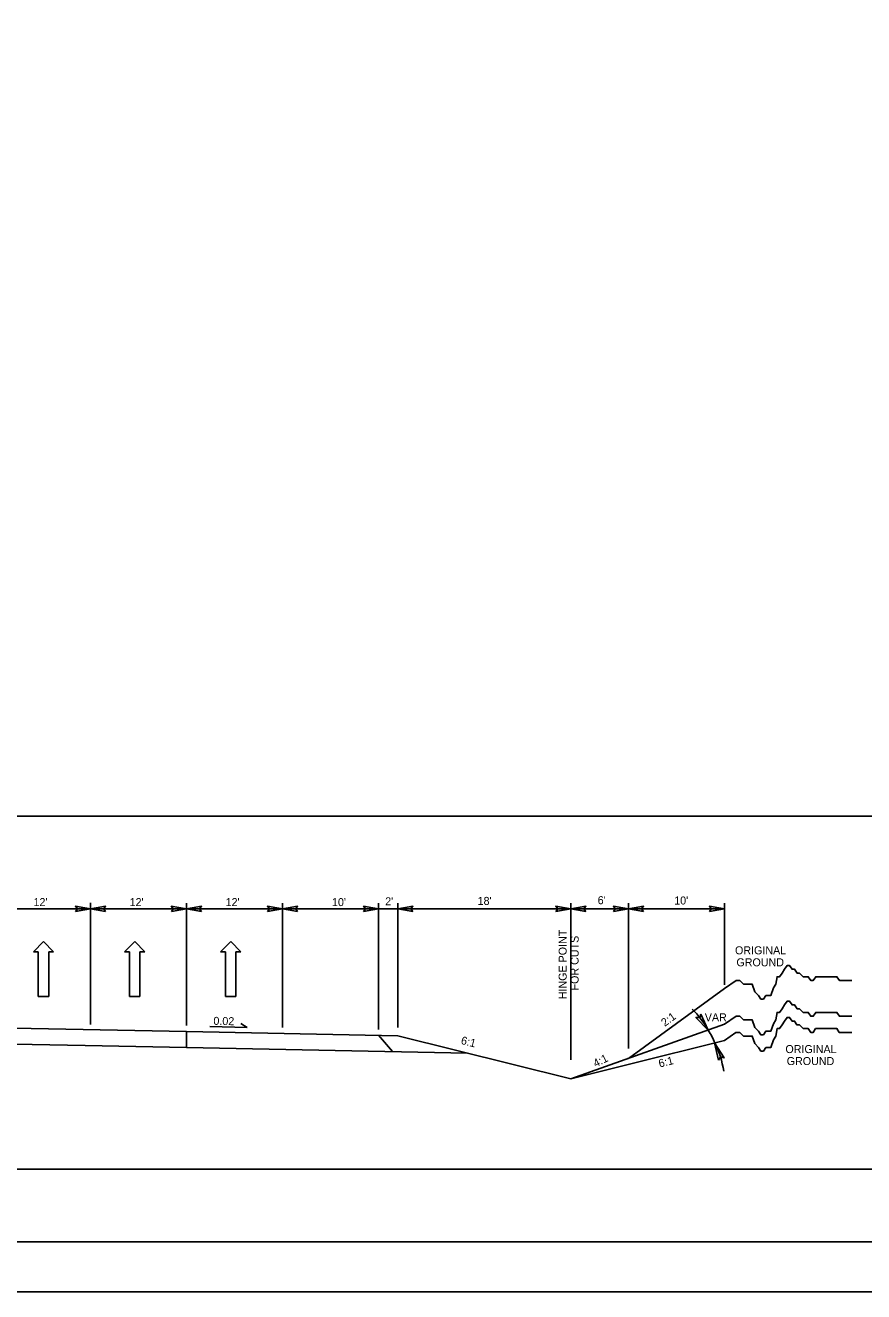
# Model space of a CAD drawing. Extents: x 1636954 to 1644154, y 841334 to 845582.
# Drawn here: x 1638748 to 1639588, y 841334 to 842602 of the extents above; entities that cross this region are included whole.
import ezdxf

# ---------------------------------------------------------------- set-up
doc = ezdxf.new("R2010")
doc.units = 0
for name, color, linetype in [('Default', 7, 'Continuous'), ('Prop Dimension', 7, 'Continuous'), ('Prop Dimension Text', 7, 'Continuous'), ('Prop PHM Legend CELL', 7, 'Continuous'), ('Scratch_Level_1', 7, 'Continuous'), ('Sheet Plan And Profile CELL', 7, 'Continuous'), ('Typical Hinge Slope Interstate CELL', 7, 'Continuous'), ('Typical Pavement Slope CELL', 7, 'Continuous'), ('Typical Pavement Slope Information CELL', 7, 'Continuous')]:
    doc.layers.add(name, color=color, linetype=linetype)

msp = doc.modelspace()

# ---------------------------------------------------------------- linework, layer by layer
at = {"layer": 'Default'}
for points in [[(1639424.6, 841611.9), (1639431.9, 841595.9), (1639419.5, 841608.6), (1639423.3, 841608.5)], [(1639442.1, 841565.9), (1639438.3, 841583.1), (1639447.7, 841568.1), (1639444.1, 841569)], [(1639442.1, 841565.9), (1639438.3, 841583.1), (1639447.7, 841568.1), (1639444.1, 841569)]]:
    msp.add_lwpolyline(points, close=True, dxfattribs=at)
at = {"layer": 'Prop Dimension'}
for p, q in [((1638813, 841601.4), (1638813, 841723.4)), ((1638909.1, 841600.5), (1638909.1, 841723.2)), ((1639005.3, 841598.5), (1639005.3, 841723.2)), ((1639101.6, 841598.5), (1639101.6, 841723.2)), ((1639101.6, 841596.6), (1639101.6, 841723.2)), ((1639120.8, 841598.5), (1639120.8, 841723.2)), ((1639294.2, 841566.1), (1639294.2, 841723.2)), ((1639351.9, 841577.4), (1639351.9, 841723.2)), ((1639448.2, 841641.4), (1639448.2, 841723.2)), ((1638716.7, 841717.3), (1638813, 841717.3)), ((1638813, 841717.3), (1638909.2, 841717.3)), ((1638909.2, 841717.3), (1639005.5, 841717.3)), ((1639005.5, 841717.3), (1639101.7, 841717.3)), ((1639005.5, 841717.3), (1639101.7, 841717.3)), ((1639101.7, 841717.3), (1639120.8, 841717.3)), ((1639120.8, 841717.3), (1639294.1, 841717.3)), ((1639294.1, 841717.3), (1639351.8, 841717.3)), ((1639351.8, 841717.3), (1639448.1, 841717.3)), ((1638765.9, 841684.5), (1638755.7, 841674.4)), ((1638775.9, 841674.4), (1638765.9, 841684.5)), ((1638857.3, 841684.5), (1638847.1, 841674.4)), ((1638867.3, 841674.4), (1638857.3, 841684.5)), ((1638953.6, 841684.5), (1638943.3, 841674.4)), ((1638963.5, 841674.4), (1638953.6, 841684.5)), ((1638755.7, 841674.4), (1638760.5, 841674.4)), ((1638760.5, 841674.4), (1638760.5, 841629.5)), ((1638771.1, 841629.5), (1638771.1, 841674.4)), ((1638771.1, 841674.4), (1638775.9, 841674.4)), ((1638847.1, 841674.4), (1638851.9, 841674.4)), ((1638851.9, 841674.4), (1638851.9, 841629.5)), ((1638862.4, 841629.5), (1638862.4, 841674.4)), ((1638862.4, 841674.4), (1638867.3, 841674.4)), ((1638943.3, 841674.4), (1638948.1, 841674.4)), ((1638948.1, 841674.4), (1638948.1, 841629.5)), ((1638958.7, 841629.5), (1638958.7, 841674.4)), ((1638958.7, 841674.4), (1638963.5, 841674.4)), ((1638760.5, 841629.5), (1638771.1, 841629.5)), ((1638851.9, 841629.5), (1638862.4, 841629.5)), ((1638948.1, 841629.5), (1638958.7, 841629.5))]:
    msp.add_line(p, q, dxfattribs=at)
for points in [[(1638797.9, 841714.7), (1638813, 841717.3), (1638797.8, 841720), (1638799.8, 841717.3)], [(1638828, 841714.7), (1638813, 841717.3), (1638828.1, 841720), (1638826.2, 841717.3)], [(1638894, 841714.7), (1638909.1, 841717.3), (1638893.9, 841720), (1638895.9, 841717.3)], [(1638924.1, 841714.7), (1638909.1, 841717.3), (1638924.2, 841720), (1638922.2, 841717.3)], [(1638990.3, 841714.7), (1639005.3, 841717.3), (1638990.2, 841720), (1638992.1, 841717.3)], [(1639020.3, 841714.7), (1639005.3, 841717.3), (1639020.4, 841720), (1639018.5, 841717.3)], [(1639086.5, 841714.7), (1639101.6, 841717.3), (1639086.5, 841720), (1639088.4, 841717.3)], [(1639135.9, 841714.7), (1639120.8, 841717.3), (1639135.9, 841720), (1639134, 841717.3)], [(1639279.1, 841714.7), (1639294.2, 841717.3), (1639279, 841720), (1639281, 841717.3)], [(1639309.2, 841714.7), (1639294.2, 841717.3), (1639309.3, 841720), (1639307.3, 841717.3)], [(1639336.9, 841714.7), (1639351.9, 841717.3), (1639336.8, 841720), (1639338.7, 841717.3)], [(1639366.9, 841714.7), (1639351.9, 841717.3), (1639367, 841720), (1639365.1, 841717.3)], [(1639433.1, 841714.7), (1639448.1, 841717.3), (1639433, 841720), (1639434.9, 841717.3)]]:
    msp.add_lwpolyline(points, close=True, dxfattribs=at)
at = {"layer": 'Prop PHM Legend CELL'}
msp.add_line((1637654.2, 841456.6), (1640851.7, 841456.6), dxfattribs=at)
msp.add_lwpolyline([(1637654.2, 841810.2), (1639599.4, 841810.2), (1639599.4, 841383.9), (1637654.2, 841383.9)], close=True, dxfattribs=at)
at = {"layer": 'Scratch_Level_1'}
msp.add_lwpolyline([(1636954.2, 841333.9), (1636954.2, 844733.9), (1644154.2, 844733.9), (1644154.2, 841333.9)], close=True, dxfattribs=at)
at = {"layer": 'Sheet Plan And Profile CELL'}
msp.add_lwpolyline([(1637004.2, 841383.9), (1637004.2, 844683.9), (1644104.2, 844683.9), (1644104.2, 841383.9)], close=True, dxfattribs=at)
at = {"layer": 'Typical Hinge Slope Interstate CELL'}
for p, q in [((1639448.1, 841637.5), (1639352, 841567.6)), ((1639294.1, 841547), (1639448.1, 841601.7)), ((1639101.6, 841590.7), (1639115.4, 841574.4)), ((1639120.8, 841590.3), (1639294.1, 841547)), ((1639351.8, 841561.4), (1639448.1, 841585.5)), ((1639351.8, 841561.4), (1639294.1, 841547))]:
    msp.add_line(p, q, dxfattribs=at)
for points in [[(1639448.1, 841637.5), (1639459.7, 841645.6), (1639463.4, 841645.6), (1639467.2, 841641.9), (1639469.7, 841641.9), (1639473.4, 841641.9), (1639475.9, 841641.9), (1639478.4, 841634.4), (1639482.2, 841630.6), (1639484.7, 841626.9), (1639487.1, 841626.9), (1639489.6, 841630.6), (1639492.1, 841630.6), (1639494.6, 841630.6), (1639497.1, 841638.1), (1639499.6, 841641.9), (1639500.9, 841649.4), (1639503.4, 841649.4), (1639505.9, 841653.1), (1639508.4, 841656.9), (1639510.9, 841660.6), (1639513.4, 841660.6), (1639515.9, 841656.9), (1639518.4, 841656.9), (1639520.9, 841653.1), (1639523.3, 841653.1), (1639527.1, 841649.4), (1639529.6, 841649.4), (1639532.1, 841649.4), (1639534.6, 841645.6), (1639537.1, 841645.6), (1639539.6, 841649.4), (1639542.1, 841649.4), (1639544.6, 841649.4), (1639547.1, 841649.4), (1639549.6, 841649.4), (1639553.3, 841649.4), (1639557.1, 841649.4), (1639560.8, 841649.4), (1639563.3, 841645.6), (1639567, 841645.6), (1639570.8, 841645.6), (1639575.8, 841645.6)], [(1639448.1, 841601.7), (1639459.7, 841609.8), (1639463.4, 841609.8), (1639467.2, 841606.1), (1639469.7, 841606.1), (1639473.4, 841606.1), (1639475.9, 841606.1), (1639478.4, 841598.6), (1639482.2, 841594.9), (1639484.7, 841591.1), (1639487.1, 841591.1), (1639489.6, 841594.9), (1639492.1, 841594.9), (1639494.6, 841594.9), (1639497.1, 841602.3), (1639499.6, 841606.1), (1639500.9, 841613.6), (1639503.4, 841613.6), (1639505.9, 841617.3), (1639508.4, 841621.1), (1639510.9, 841624.8), (1639513.4, 841624.8), (1639515.9, 841621.1), (1639518.4, 841621.1), (1639520.9, 841617.3), (1639523.3, 841617.3), (1639527.1, 841613.6), (1639529.6, 841613.6), (1639532.1, 841613.6), (1639534.6, 841609.8), (1639537.1, 841609.8), (1639539.6, 841613.6), (1639542.1, 841613.6), (1639544.6, 841613.6), (1639547.1, 841613.6), (1639549.6, 841613.6), (1639553.3, 841613.6), (1639557.1, 841613.6), (1639560.8, 841613.6), (1639563.3, 841609.8), (1639567, 841609.8), (1639570.8, 841609.8), (1639575.8, 841609.8)], [(1639448.1, 841585.5), (1639459.6, 841593.6), (1639463.4, 841593.6), (1639467.1, 841589.9), (1639469.6, 841589.9), (1639473.4, 841589.9), (1639475.9, 841589.9), (1639478.4, 841582.4), (1639482.1, 841578.6), (1639484.6, 841574.9), (1639487.1, 841574.9), (1639489.6, 841578.6), (1639492.1, 841578.6), (1639494.6, 841578.6), (1639497.1, 841586.1), (1639499.6, 841589.9), (1639500.8, 841597.4), (1639503.3, 841597.4), (1639505.8, 841601.1), (1639508.3, 841604.9), (1639510.8, 841608.6), (1639513.3, 841608.6), (1639515.8, 841604.9), (1639518.3, 841604.9), (1639520.8, 841601.1), (1639523.3, 841601.1), (1639527, 841597.4), (1639529.5, 841597.4), (1639532, 841597.4), (1639534.5, 841593.6), (1639537, 841593.6), (1639539.5, 841597.4), (1639542, 841597.4), (1639544.5, 841597.4), (1639547, 841597.4), (1639549.5, 841597.4), (1639553.3, 841597.4), (1639557, 841597.4), (1639560.8, 841597.4), (1639563.2, 841593.6), (1639567, 841593.6), (1639570.7, 841593.6), (1639575.7, 841593.6)]]:
    msp.add_lwpolyline(points, dxfattribs=at)
for centre, start, end in [((1639347.9, 841547.9), 29.7519, 45.5036), ((1639351.8, 841539.8), 8.9538, 26.5701), ((1639351.8, 841539.8), 8.9538, 26.5701)]:
    msp.add_arc(centre, 96.8, start, end, dxfattribs=at)
msp.add_ellipse((1639350.9, 841600.8), major_axis=(87.3, -41.7), ratio=0.5, start_param=0.463735, end_param=0.681536, dxfattribs=at)
at = {"layer": 'Typical Pavement Slope CELL'}
for p, q in [((1638909.1, 841594.5), (1638533.6, 841602)), ((1639120.8, 841590.3), (1638909.1, 841594.5)), ((1638909.1, 841578.5), (1638909.1, 841594.5)), ((1638807.6, 841580.5), (1638533.6, 841586)), ((1638909.1, 841578.5), (1638807.6, 841580.5)), ((1639190.5, 841572.9), (1638909.1, 841578.5))]:
    msp.add_line(p, q, dxfattribs=at)
at = {"layer": 'Typical Pavement Slope Information CELL'}
for q in [(1638932.6, 841599.4), (1638963.7, 841602.4)]:
    msp.add_line((1638969.9, 841598.6), q, dxfattribs=at)

# ---------------------------------------------------------------- texts
at = {"layer": 'Prop Dimension Text'}
for s, p in [("18'", (1639200.8, 841721.3)), ("6'", (1639321.1, 841722)), ("10'", (1639397.8, 841721.7)), ('ORIGINAL', (1639458.7, 841671.8)), ('GROUND', (1639460.1, 841659.8)), ('VAR', (1639428.4, 841604.7)), ('ORIGINAL', (1639509.2, 841572.9)), ('GROUND', (1639510.5, 841560.9))]:
    msp.add_text(s, height=8.02, dxfattribs=at).set_placement(p)
for s, height, rotation, p in [('HINGE POINT', 8.016, 90, (1639290, 841626.8)), ('FOR CUTS', 8.02, 90, (1639302, 841635.6)), ('2:1', 8.02, 36.0298, (1639388.3, 841599.1)), ('6:1', 8.02, 345.9638, (1639183.5, 841582.1)), ('4:1', 8.02, 26.5701, (1639319, 841558.4)), ('6:1', 8.02, 14.0381, (1639383.2, 841558.4))]:
    msp.add_text(s, height=height, rotation=rotation, dxfattribs=at).set_placement(p)
at = {"layer": 'Typical Pavement Slope Information CELL'}
for s, p in [("12'", (1638755.8, 841720.1)), ("12'", (1638852.1, 841720.1)), ("12'", (1638948.3, 841720.1)), ("10'", (1639054.9, 841720.1)), ("2'", (1639108.2, 841720.9))]:
    msp.add_text(s, height=8.02, dxfattribs=at).set_placement(p)
msp.add_text('0.02', height=8.02, rotation=358.8543, dxfattribs=at).set_placement((1638936, 841601.2))

doc.saveas('drawing.dxf')
